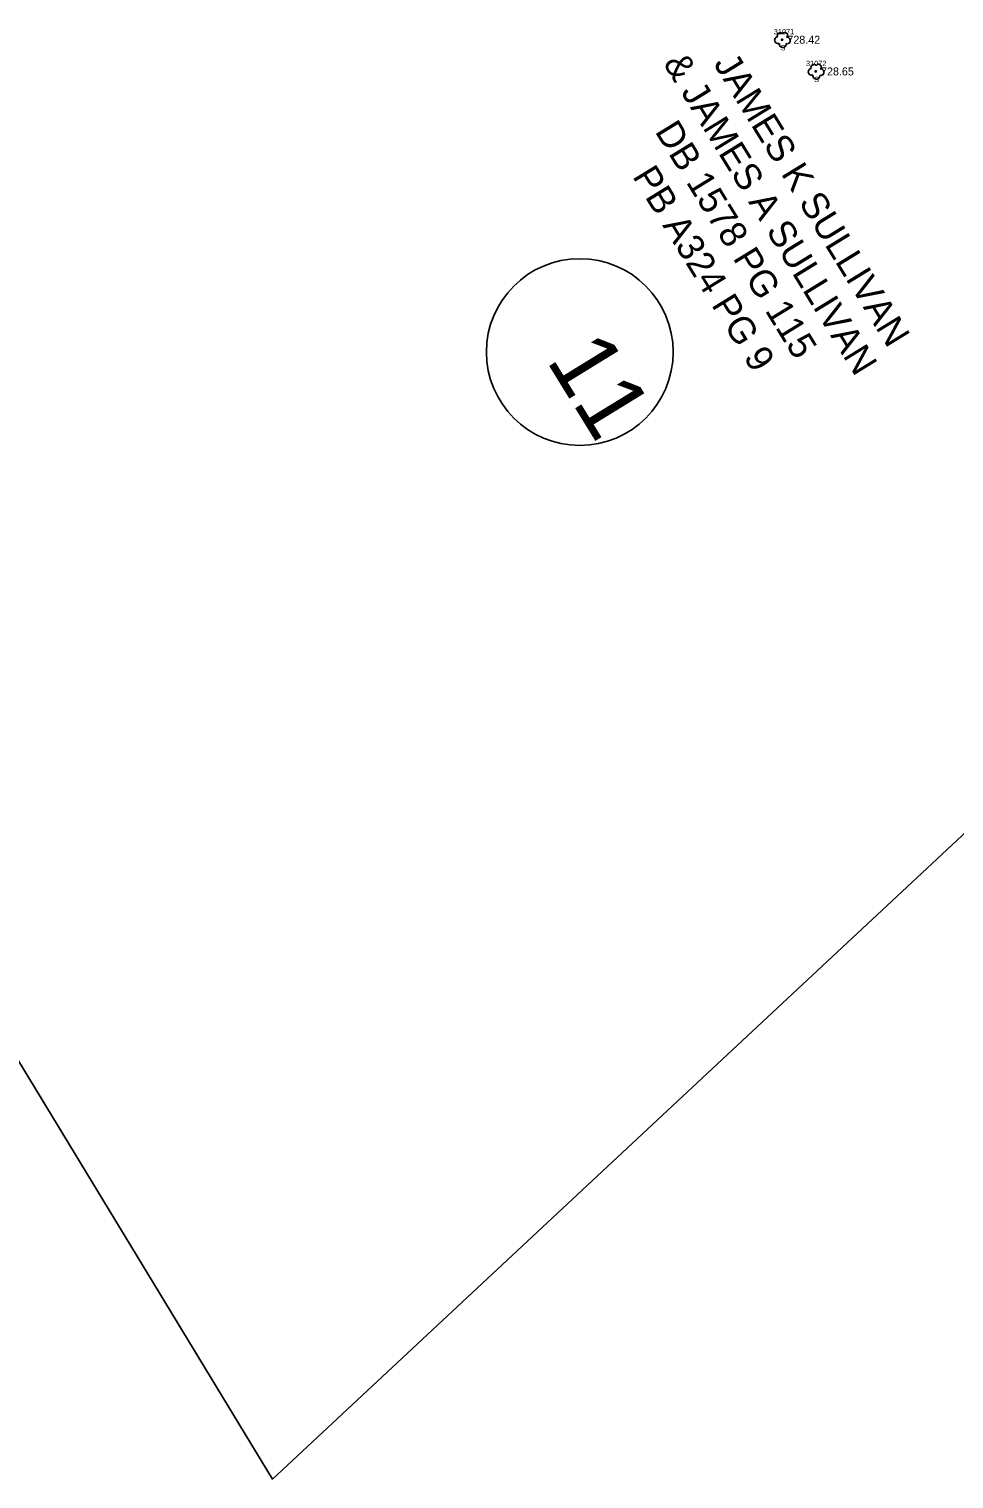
# Model space of a CAD drawing. Extents: x 1375131 to 1378678, y 999028 to 1004053.
# Drawn here: x 1377519.9 to 1377693.3, y 1000687.8 to 1000959.6 of the extents above; entities that cross this region are included whole.
import ezdxf

# ---------------------------------------------------------------- set-up
doc = ezdxf.new("R2010")
doc.units = 0
for name, color, linetype in [('RD_EX_DV_Prop', 7, 'Continuous'), ('RD_EX_DV_TX_Prop(Owner ID)', 7, 'Continuous'), ('RD_EX_TX_VEG_ELEV', 7, 'Continuous'), ('RD_EX_VEG', 7, 'Continuous'), ('RD_EX_VEG_txCode', 7, 'Continuous'), ('RD_SMD_Locator', 7, 'Continuous')]:
    doc.layers.add(name, color=color, linetype=linetype)

msp = doc.modelspace()

# ---------------------------------------------------------------- linework, layer by layer
at = {"layer": 'RD_EX_DV_Prop'}
msp.add_lwpolyline([(1377790.33, 1000897.55), (1377565.52, 1000687.8), (1377429.72, 1000911.35), (1377444.43, 1000925.1)], dxfattribs=at)
at = {"layer": 'RD_EX_DV_TX_Prop(Owner ID)'}
msp.add_circle((1377623.12, 1000899), 17.5, dxfattribs=at)
at = {"layer": 'RD_EX_VEG'}
for centre in [(1377661.03, 1000957.54), (1377667.34, 1000951.6)]:
    msp.add_circle(centre, 0.125, dxfattribs=at)
for centre, radius, start, end in [((1377660.25, 1000957.46), 0.628, 96.4518, 294.734), ((1377660.67, 1000958.31), 0.542, 34.9763, 204.756), ((1377661.56, 1000958.39), 0.497, 308.7626, 152.0467), ((1377661.95, 1000957.4), 0.609, 256.5667, 98.1046), ((1377661.16, 1000956.74), 0.659, 166.8827, 5.7589), ((1377666.56, 1000951.52), 0.628, 96.4518, 294.734), ((1377666.98, 1000952.37), 0.542, 34.9763, 204.756), ((1377667.86, 1000952.45), 0.497, 308.7626, 152.0467), ((1377668.26, 1000951.46), 0.609, 256.5667, 98.1046), ((1377667.46, 1000950.8), 0.659, 166.8827, 5.7589)]:
    msp.add_arc(centre, radius, start, end, dxfattribs=at)
at = {"layer": 'RD_SMD_Locator'}
for centre in [(1377661.03, 1000957.54), (1377667.34, 1000951.6)]:
    msp.add_circle(centre, 0.075, dxfattribs=at)

# ---------------------------------------------------------------- texts
at = {"layer": 'RD_EX_DV_TX_Prop(Owner ID)'}
for s, height, p in [('& JAMES A SULLIVAN', 5, (1377638.66, 1000953.11)), ('JAMES K SULLIVAN', 5, (1377648.09, 1000953.04)), ('DB 1578 PG 115', 5, (1377637.1, 1000940.37)), ('PB A324 PG 9', 5, (1377632.89, 1000931.94)), ('11', 12.5, (1377616.72, 1000897.49))]:
    msp.add_text(s, height=height, rotation=301.5778, dxfattribs=at).set_placement(p)
at = {"layer": 'RD_EX_TX_VEG_ELEV'}
for s, p in [('728.42', (1377662.03, 1000956.79)), ('728.65', (1377668.34, 1000950.85))]:
    msp.add_text(s, height=1.5, dxfattribs=at).set_placement(p)
at = {"layer": 'RD_EX_VEG_txCode'}
for s, p in [('31071', (1377659.48, 1000958.54)), ('S', (1377660.73, 1000955.54)), ('31072', (1377665.51, 1000952.6)), ('S', (1377667.03, 1000949.6))]:
    msp.add_text(s, height=1, dxfattribs=at).set_placement(p)

doc.saveas('drawing.dxf')
